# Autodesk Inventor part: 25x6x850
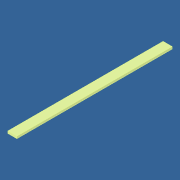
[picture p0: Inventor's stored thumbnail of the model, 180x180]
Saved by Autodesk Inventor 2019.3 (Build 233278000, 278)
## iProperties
Created: 2019-02
Part Number: 25x6x850
Material: Ocel, měkká, svařovaná
Document SubType Name: Modeling
Designer: B-hon
Density: 7.85 g/cm^3
Appearance: Zinek – chromovaný 2
Author: B-hon
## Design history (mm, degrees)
sketch "Náčrt1"
  geometry: L1 (-12.5, 3)-(12.5, 3); L2 (12.5, 3)-(12.5, -3); L3 (12.5, -3)-(-12.5, -3); L4 (-12.5, -3)-(-12.5, 3); L5 (-12.5, 3)-(12.5, -3); L6 (12.5, 3)-(-12.5, -3); 1 further point
  constraints: 12 end point, 2 midpoint, 2 parallel, 1 horizontal, 1 perpendicular
  dimensions: "d0" = 25 distance of L2.end L3.end; "d1" = 6 distance of L1.end L2.end
extrude "Vysunutí1" new body sketch "Náčrt1" distance "d2" = 425; taper "d3" = 0 deg
node "Těleso1"
